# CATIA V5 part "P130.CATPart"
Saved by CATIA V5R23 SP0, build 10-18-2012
Part number: P130
Definition: Anneau Elastique Ø7
Material "Acier": density 7860 kg/m3, Young's modulus 2e+11 Pa, Poisson ratio 0.266, thermal expansion 1.17e-05 1/K
Bounding box of the stored display mesh (mm): x -4.473 to 4.473, y -6.41 to 4.75, z 0 to 0.8
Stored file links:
  C:\wamp\www\COURS\CONCEPTION GMP1\TITRE 02-SEMESTRE 2\03-TP7-PRESSE MECANIQUE\eleve\P130.CATPart
  L:\standards\circlips\Circlips_ext.txt
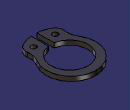
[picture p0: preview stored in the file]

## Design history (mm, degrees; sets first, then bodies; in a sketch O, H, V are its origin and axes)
Parameters
  diam_arbre = 7 mm
  s_largeur = 0.8 mm
  a = 3.1 mm
  b = 1.4 mm
  c = 13.8 mm
  diam_trou = 1 mm
  D_gorge = 6.7 mm
  largeur_gorge = 0.9 mm
  reserve_matiere = 0.5 mm
  arrondi = 1 mm
  Resistance_anneau = 260 (force)
  Resistance_gorge = 500 (force)
  `N-maxi` = 75000 (angularspindlespeed)
  `Capacité_anneau-arrondi_g` = 2.4 (force)
Body1 (main body), material "Acier"
  Sketch1 on xy-plane, origin (0, 0, 0), H (1, 0, 0), V (0, 1, 0)
    arc A1 centre (0, 0) radius 3.35 from (0.5167, -3.3099) to (0, 3.35) ccw
    line L1 (0.5167, -3.3099) -> (0.5167, -6.4099)
    point P1 (0.5167, -6.4099)
    point P2 (0.5167, -3.3099)
    circle A2 centre (1.9428, -4.5269) radius 0.5
    point P4 (2.2167, -1.9271)
    point P5 (0, 3.35)
    point P7 (0, 3.35)
    circle A3 centre (-1.9428, -4.5269) radius 0.5
    construction circle A4 centre (0, 0) radius 3.5
    point P9 (0, 1.4)
    construction circle A5 centre (0, -0.8419) radius 5.5919
    point P10 (0, -0.8419)
    arc A6 centre (0, -0.8419) radius 5.5919 from (0.5167, -6.4099) to (2.608, -5.7884) ccw
    point P11 (0, -0.8419)
    arc A7 centre (1.9428, -4.5269) radius 1.4262 from (2.608, -5.7884) to (3.3489, -4.2881) ccw
    point P13 (2.608, -5.7884)
    point P14 (0.5167, -6.4099)
    arc A8 centre (0, 0.275) radius 4.475 from (0, 4.75) to (3.7839, -2.1141) cw
    point P15 (0, 0.275)
    arc A9 centre (6.4051, -3.7691) radius 3.1 from (3.7839, -2.1141) to (3.3489, -4.2881) ccw
    point P16 (3.3489, -4.2881)
    point P18 (0, 4.75)
    point P19 (3.7839, -2.1141)
    point P21 (0, 3.35)
    point P22 (-3.3489, -4.2881)
    point P23 (-3.7839, -2.1141)
    arc A10 centre (-6.4051, -3.7691) radius 3.1 from (-3.7839, -2.1141) to (-3.3489, -4.2881) cw
    point P25 (0, 4.75)
    arc A11 centre (0, 0.275) radius 4.475 from (0, 4.75) to (-3.7839, -2.1141) ccw
    point P27 (-2.608, -5.7884)
    arc A12 centre (-1.9428, -4.5269) radius 1.4262 from (-2.608, -5.7884) to (-3.3489, -4.2881) cw
    point P29 (-0.5167, -6.4099)
    arc A13 centre (0, -0.8419) radius 5.5919 from (-0.5167, -6.4099) to (-2.608, -5.7884) cw
    point P31 (-0.5167, -3.3099)
    line L2 (-0.5167, -3.3099) -> (-0.5167, -6.4099)
    point P32 (0, 3.35)
    arc A14 centre (0, 0) radius 3.35 from (-0.5167, -3.3099) to (0, 3.35) cw
    radius A1 = 3.35 {= D_gorge /2}
    distance V L1 = 0.5167 {= a /6}
    radius A2 = 0.5 {= diam_trou /2}
    radius A4 = 3.5 {= diam_arbre /2}
    distance P2 P1 = 3.1 {= a}
    distance A8 A4 = 0.7 {= Sketch1.distance(P5 A8) /2}
    distance P5 A8 = 1.4 {= b}
    radius A9 = 3.1 {= Sketch1.distance(P2 P1)}
    coincidence: P5 V, P5 P7, P1 L1, P1 A5, P10 V, P11 V, A6 A5, P15 V, P18 V
    symmetry: P5 P7 V, A2 A3 V, P7 P21 V, A9 A10 V, A8 A11 V, A7 A12 V, A6 A13 V, L1 L2 V, A1 A14 V, P19 P23 V, P16 P22 V, P18 P25 V, P13 P27 V, P14 P29 V, P2 P31 V, P5 P32 V
    concentricity: A4 A1, A2 A7
    tangency: A7 A6, A7 L1, A4 A7, A8 A5, A9 A8, A9 A7
  Pad1: profile Sketch1, direction (0, 0, 1), length 0.8 {= s_largeur}
Relations
  Sketch1.distance(P2 P1) = a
